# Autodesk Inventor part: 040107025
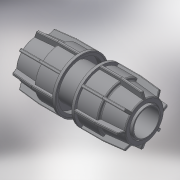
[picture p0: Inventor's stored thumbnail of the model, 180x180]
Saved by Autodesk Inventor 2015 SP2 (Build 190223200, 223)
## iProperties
Created: 2017-08
Part Number: 040107025
Material: Generic
Description: PLASSON IRRIFIT COUPLER 25-25
Document SubType Name: Modeling
Designer: KIM
Density: 1 g/cm^3
Appearance: Default
Author: KIM
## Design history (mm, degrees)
derived "040107.ipt"
feature "Solid1::040107.ipt"
tag "TaggingFeature1"
body "Solid1"
other parameters: "d5" = 36.4, "d6" = 18.7, "d10" = 45, "d22" = 35, "d24" = 1.955, "d25" = 40.5, "d26" = 36, "d31" = 1, "d49" = 2.25, "d50" = 0, "d58" = 0.5, "d61" = 360 deg, "d77" = 25, "d78" = 5 deg, "d80" = 27.5, "d81" = 42.5, "d82" = 2.55, "d84" = 5 deg, "d85" = 70 deg, "d86" = 42.75, "d87" = 0.425, "d88" = 0, "d89" = 38.25, "d90" = 4.25, "d91" = 0, "d93" = 180 deg, "d_" = 25, "E_" = 45, "H_" = 85, "l_nut" = 36.4
